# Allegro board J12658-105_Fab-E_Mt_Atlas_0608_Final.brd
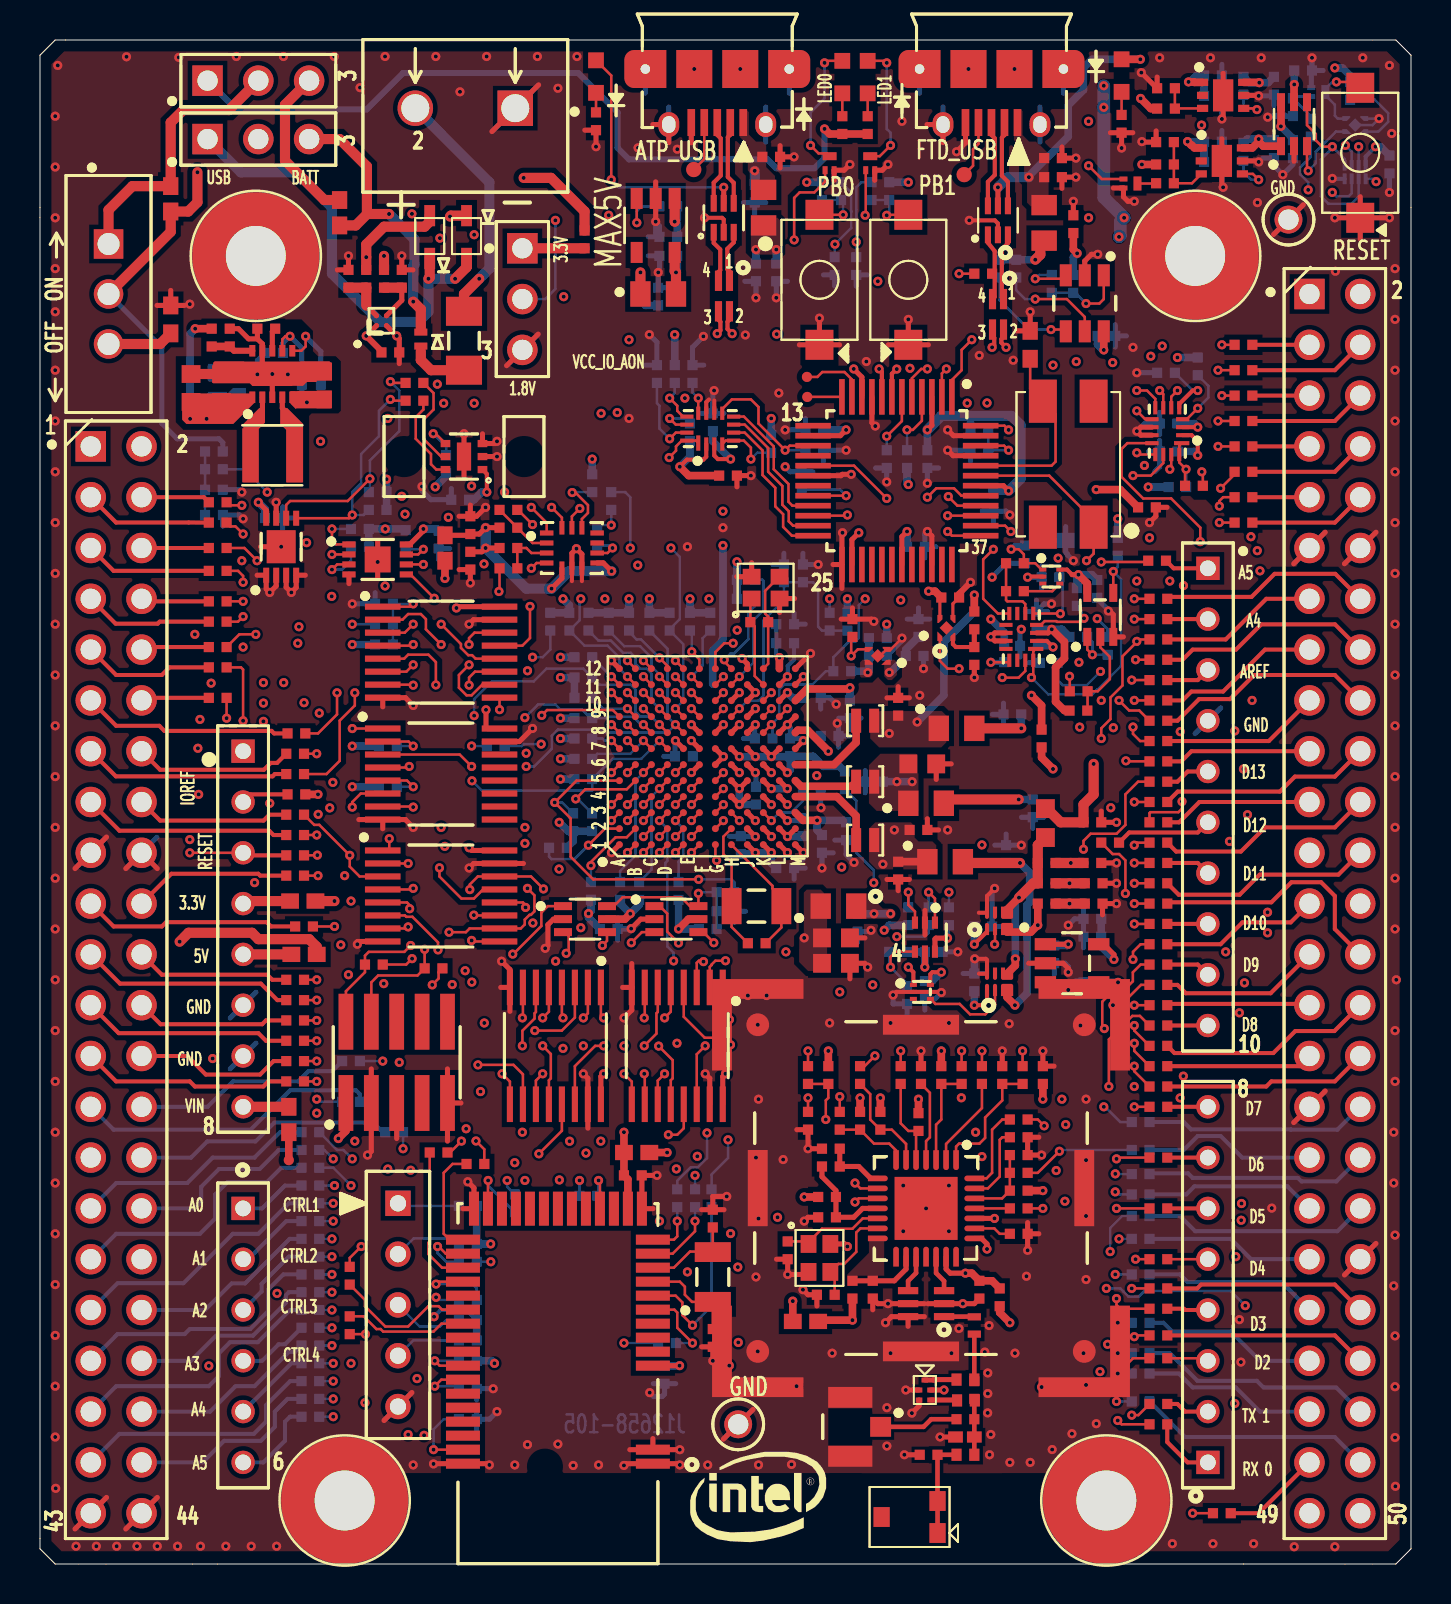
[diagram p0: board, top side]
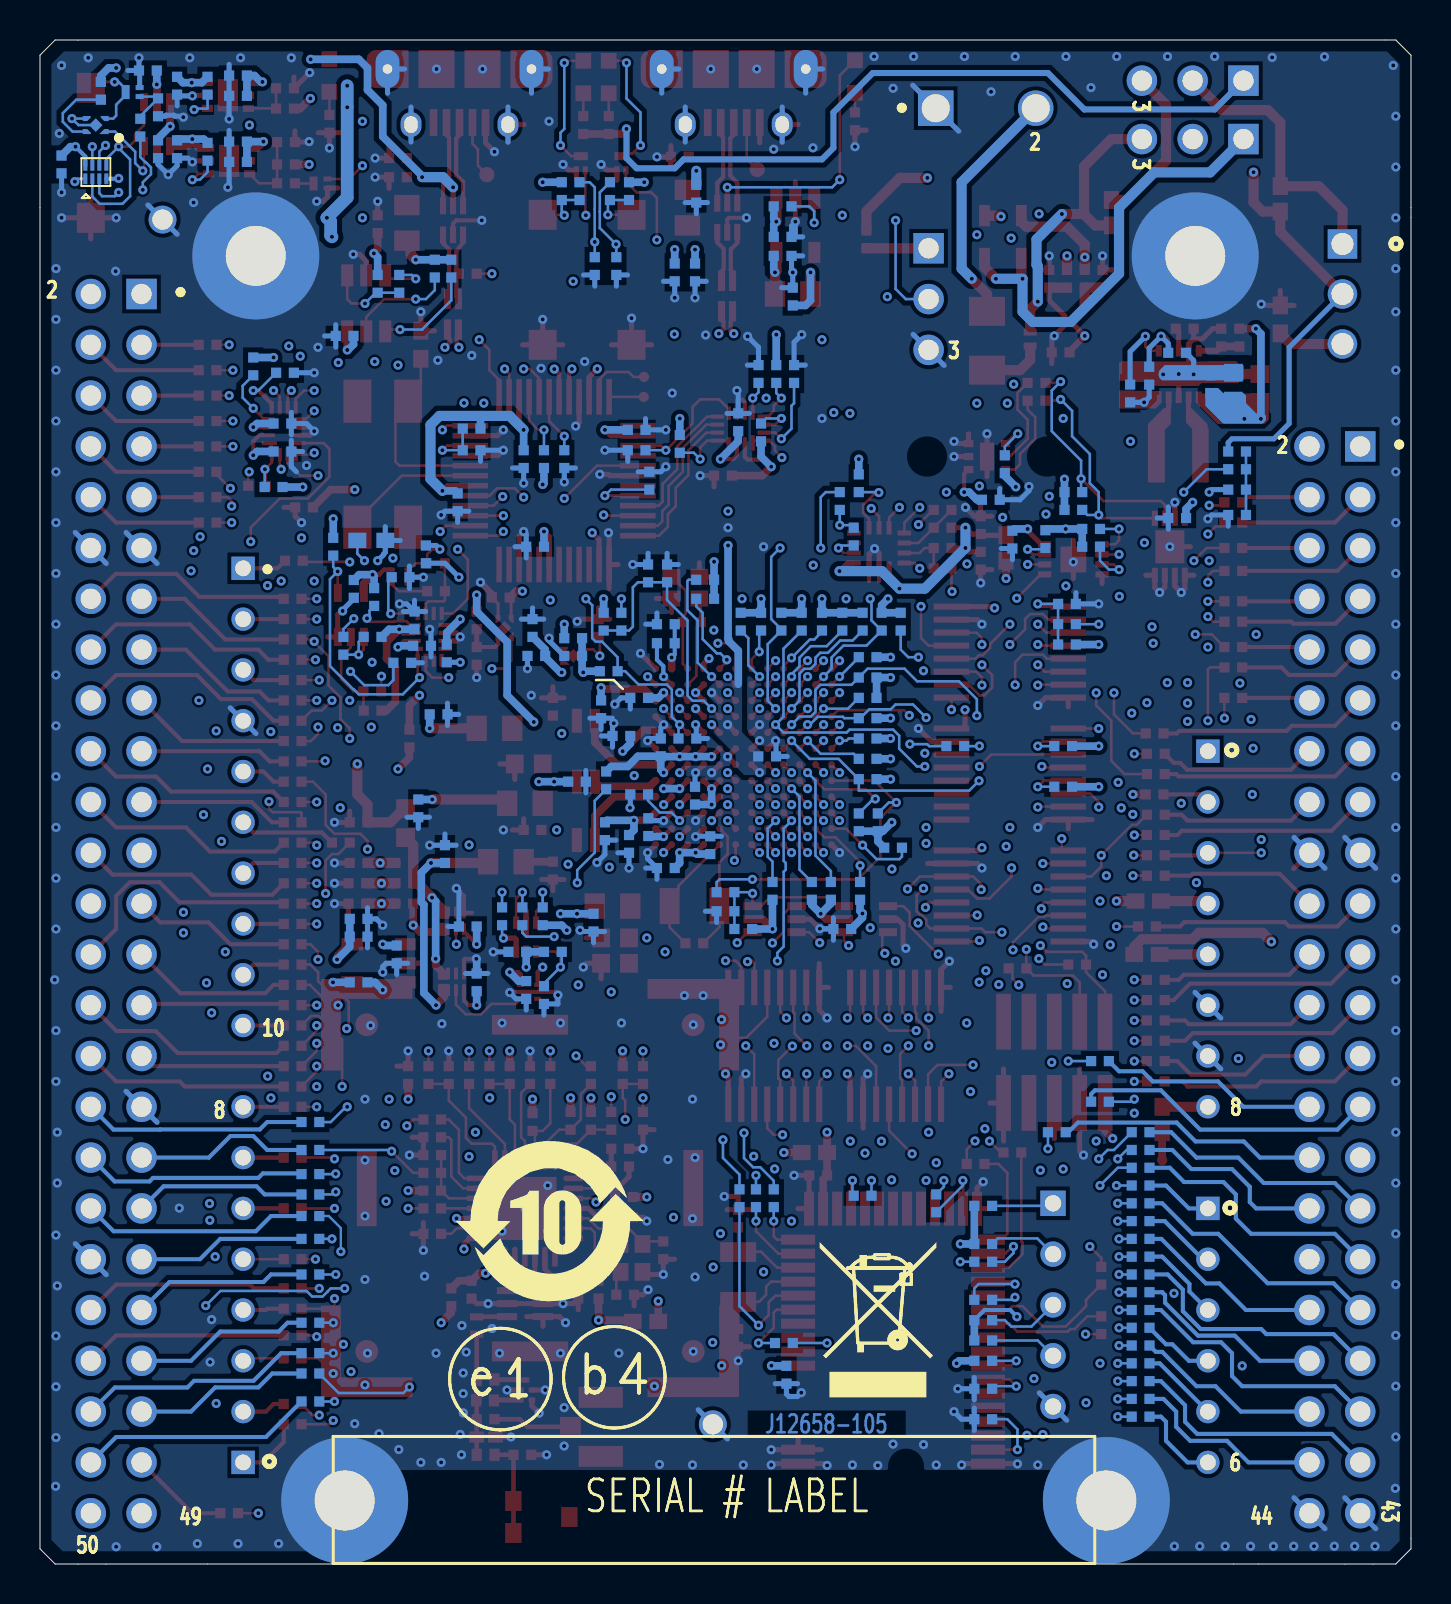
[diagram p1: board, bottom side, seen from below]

Outline 68.58 x 76.2 mm; copper layers: TOP, LAYER2_GND, L3_SIG, L4_SIG, LAYER5_PWR, BOTTOM. Coordinates in mm from the lower left corner of the outline.
Outline path: 0,75.44 0,0.76 0.76,0 67.82,0 68.58,0.76 68.58,75.44 67.82,76.2 0.76,76.2 0,75.44

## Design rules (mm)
net group AP_USB: nets AP_USB_DN AP_USB_DP
net group D_PR: nets D+PR D-PR
net group DPM: nets DM DP
net group FT_D: nets FT_D+P FT_D-P
net group FTD: nets FTD_DM FTD_DP
net group USB_FTD_D: nets USB_FTD_DM USB_FTD_DP
nets with their own width: min track width 0.102; nets VCC_AON_1P8

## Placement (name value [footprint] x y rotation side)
C1  0.1 uF  [SMC0402IA]  36.13 70.36 0 top
C2  0.1 uF  [SMC0402IA]  50.23 70.29 0 top
C3  0.1 uF  [SMC0402IA]  51.69 66.55 90 top
C4  0.1 uF  [SMC0402IA]  15.43 63.82 90 top
C5  0.1 uF  [SMC0402IA]  18.1 63.82 90 top
C6  18pF  [SMC0603IA]  49.53 60.26 90 top
C7  10uF  [SMC0603IA]  14.22 58.23 90 top
C8  4.7UF  [SMC0402IA]  17.08 60.58 0 top
C9  0.1 uF  [SMC0402IA]  49.09 42.48 180 bottom
C10  10uF  [SMC0603IB]  9.08 58.1 90 top
C11  10uF  [SMC0603IB]  8.89 58.17 90 bottom
C12  10uF  [SMC0603IB]  7.56 58.1 90 top
C13  4.7UF  [SMC0402IA]  54.93 52.83 0 top
C14  0.1uF  [SMC0402IA]  21.53 51.5 90 top
C15  0.1uF  [SMC0402IA]  21.53 50.61 270 top
C16  18pF  [SMC0603IA]  52.71 51.18 180 bottom
C17  0.1 uF  [SMC0402IA]  43.94 46.35 90 bottom
C18  1uF  [SMC0402IA]  43.31 45.4 0 bottom
C19  10uF  [SMC0603IB]  43.43 40 0 top
C20  4.7UF  [SMC0402IA]  42.93 42.42 90 top
C21  4.7UF  [SMC0402IA]  43.5 36.7 0 top
C22  1uF  [SMC0402IA]  52.2 35.05 0 top
C23  4.7UF  [SMC0402IA]  52.2 37.08 0 top
C24  4.7UF  [SMC0402IA]  52.26 33.02 0 top
C25  4.7UF  [SMC0402IA]  40.32 37.08 270 bottom
C26  1uF  [SMC0402IA]  52.26 34.04 0 top
C27  10uF  [SMC0603IB]  39.12 31.31 0 top
C28  0.1uF  [SMC0402IA]  11.25 52.3 0 bottom
C29  0.1uF  [SMC0402IA]  19.94 51.66 270 bottom
C30  10uF  [SMC0603IB]  39.12 30.04 0 top
C31  1uF  [SMC0402IA]  50.16 24 90 top
C32  0.1uF  [SMC0402IA]  48.51 21.34 0 top
C33  0.1uF  [SMC0402IA]  40.01 20.76 180 top
C34  0.1uF  [SMC0402IA]  29.21 19.43 0 top
C35  0.1uF  [SMC0402IA]  39.81 17.34 180 top
C36  12pF  [SMC0402IA]  33.66 16.83 90 top
C37  12pF  [SMC0402IA]  37.4 16.13 270 top
C38  0.1uF  [SMC0402IA]  41.66 14.16 270 top
C39  0.1uF  [SMC0402IA]  46.99 14.16 270 top
C40  12pF  [SMC0402IA]  39.75 13.46 180 top
C41  12pF  [SMC0402IA]  33.66 11.75 270 top
C42  2.2pF  [SMC0402IB]  46.74 6.35 180 top
C43  0.1uF  [SMC0402IA]  44.89 5.46 180 top
C44  1uF  [SMC0402IA]  58.23 74.42 0 bottom
C45  0.1uF  [SMC0402IA]  61.72 74.36 270 bottom
C46  0.1uF  [SMC0402IA]  58.23 73.41 0 bottom
C47  1uF  [SMC0402IA]  58.23 71.12 0 bottom
C48  0.1uF  [SMC0402IA]  61.72 71.18 270 bottom
C49  0.1uF  [SMC0402IA]  58.23 70.1 0 bottom
C50  0.1 uF  [SMC0402IA]  31.88 66.36 180 bottom
C51  0.1 uF  [SMC0402IA]  31.88 65.41 180 bottom
C52  4.7UF  [SMC0402IA]  36.83 65.02 270 bottom
C53  0.1 uF  [SMC0402IA]  35.81 65.02 270 bottom
C54  0.1 uF  [SMC0402IA]  52.9 61.4 0 bottom
C55  0.1uF  [SMC0402IA]  11.76 61.77 180 top
C56  0.1uF  [SMC0402IA]  10.03 58.55 90 bottom
C57  0.1 uF  [SMC0402IA]  56.9 57.02 180 bottom
C58  0.1 uF  [SMC0402IA]  39.18 56.71 180 bottom
C59  0.1 uF  [SMC0402IA]  47.43 55.69 180 bottom
C60  0.1 uF  [SMC0402IA]  56.9 55.63 180 bottom
C61  0.1 uF  [SMC0402IA]  44.39 55.69 270 bottom
C62  0.033uF  [SMC0402IA]  42.35 55.69 270 bottom
C63  0.1 uF  [SMC0402IA]  42.16 39.12 180 bottom
C64  1uF  [SMC0402IA]  21.46 53.21 180 bottom
C65  0.1 uF  [SMC0402IA]  47.69 53.53 270 bottom
C66  0.1 uF  [SMC0402IA]  33.66 56.64 90 bottom
C67  0.1uF  [SMC0402IA]  62.67 71.18 270 bottom
C68  0.1uF  [SMC0402IA]  67.5 70.42 270 bottom
C69  0.1 uF  [SMC0402IA]  43.37 50.86 0 bottom
C70  0.1 uF  [SMC0402IA]  33.97 54.42 0 top
C71  0.1 uF  [SMC0402IA]  49.85 46.74 90 bottom
C72  0.1uF  [SMC0402IA]  46.74 28.64 90 bottom
C73  0.1 uF  [SMC0402IA]  49.91 45.91 180 bottom
C74  0.1uF  [SMC0402IA]  36.83 46.99 0 bottom
C75  0.1uF  [SMC0402IA]  38.16 49.09 90 bottom
C76  0.1 uF  [SMC0402IA]  49.66 38.23 270 bottom
C77  0.1uF  [SMC0402IA]  40.51 43.18 270 bottom
C78  0.1uF  [SMC0402IA]  39.05 41.4 0 bottom
C79  0.1uF  [SMC0402IA]  32.65 40.38 180 bottom
C80  0.1uF  [SMC0402IA]  44.26 30.61 0 bottom
C81  0.1 uF  [SMC0402IA]  37.53 40.39 90 bottom
C82  0.1uF  [SMC0402IA]  35.81 37.97 90 bottom
C83  0.1 uF  [SMC0402IA]  38.15 36.4 90 bottom
C84  0.1 uF  [SMC0402IA]  39.12 36.45 270 bottom
C85  0.1uF  [SMC0402IA]  35.05 35.5 90 bottom
C86  0.1 uF  [SMC0402IA]  48.32 35.05 90 bottom
C87  0.1 uF  [SMC0402IA]  42.93 35.12 270 top
C88  4.7UF  [SMC0402IA]  36.83 34.8 0 bottom
C89  0.1 uF  [SMC0402IA]  28 31.75 0 bottom
C90  0.1uF  [SMC0402IA]  50.74 30.92 270 bottom
C91  0.1 uF  [SMC0402IA]  40.89 32.51 270 bottom
C92  0.1uF  [SMC0402IA]  53.09 32.26 180 bottom
C93  4.7UF  [SMC0402IA]  53.09 31.37 180 bottom
C94  1uF  [SMC0402IA]  31.24 9.91 270 bottom
C95  0.1 uF  [SMC0402IA]  20.95 7.24 0 bottom
C96  0.1uF  [SMC0402IA]  52.88 49.2 270 bottom
C97  0.1uF  [SMC0402IA]  8.25 53.72 0 bottom
C98  1uF  [SMC0402IA]  41.47 45.4 0 bottom
C99  0.1uF  [SMC0402IA]  46.74 31.88 0 bottom
C100  0.1uF  [SMC0402IA]  44.26 29.15 270 bottom
C101  0.1uF  [SMC0402IA]  46.74 45.85 270 top
C102  0.1uF  [SMC0402IA]  45.09 48.32 0 top
C103  0.1uF  [SMC0402IA]  62.74 74.68 0 bottom
C104  0.1uF  [SMC0402IA]  40.83 65.34 270 bottom
C105  0.1uF  [SMC0402IA]  39.75 65.34 270 bottom
D1  -  [SLED0603IB]  54.1 75.23 270 top
D2  -  [SLED0603IB]  27.81 75.18 270 top
D3  -  [SLEDR0603IA]  40.13 73.53 90 top
D4  -  [SLEDR16X08MA]  41.4 73.53 90 top
D6  23V  [QT_SOD_323]  21.34 65.28 90 top
D7  23V  [QT_SOD_323]  19.49 65.28 90 top
D8  PMEG2005AEL  [SCR1006MA]  19.05 61.59 270 top
F1  -  [SFU1206IA]  21.21 59.69 90 top
FB1  30OHM  [SFB0603IA]  6.54 67.62 90 top
FB2  100OHM  [SFB0805IA]  36.2 66.93 90 top
FB3  30OHM  [SFB0603IA]  14.99 68.2 270 top
FB4  100OHM  [SFB0805IA]  50.23 66.17 90 top
FB5  100OHM  [SFB0805IA]  30.04 63.5 0 top
FB6  30OHM  [SFB0603IA]  20.26 50.16 90 top
FB7  100OHM  [SFB0805IA]  43.43 38.04 0 top
FB8  100OHM  [SFB0805IA]  44.96 41.78 0 top
FB9  100OHM  [SFB0805IA]  44.39 35.12 0 top
FB10  30OHM  [SFB0603IA]  13.78 33.15 180 top
FB11  100OHM  [SFB0805IA]  40.83 32.89 180 top
FB12  30OHM  [SFB0603IA]  13.84 30.48 180 top
FB13  30OHM  [SFB0603IA]  12.45 21.59 90 top
FB14  30OHM  [SFB0603IA]  30.48 20.57 180 top
FB15  30OHM  [SFB0603IA]  37.66 12.13 0 top
FB16  120OHM  [SFB0603IB]  50.29 36.32 90 top
FL1  -  [QT_USMM_QCS5F_B9413]  44.26 8.7 270 top
HW1  -  [QT_SMCC_LEADERTECH_SMS_201]  44.07 18.8 0 top
J1  -  [QT_CN_HIROSE_ZX62D_B_5P8]  35.18 72.07 180 top
J2  -  [QT_CN_HIROSE_ZX62D_B_5P8]  48.9 72.07 180 top
J3  -  [QT_JTHI_SAMTEC_TSW_103_07_G_S]  8.38 74.17 90 top
J4  -  [HDR_TJV_1X2_50MA]  23.77 72.79 270 top
J5  -  [QT_JTHI_SAMTEC_TSW_103_07_G_S]  8.38 71.25 90 top
J6  -  [QT_JTHI_SAMTEC_TSW_103_07_G_S]  24.13 65.79 0 top
J8  -  [QT_JSMM_MOLEX_90147_1110_PTH031]  58.42 49.78 0 top
J9  -  [QT_JSMM_MOLEX_90147_1108_PTH031]  10.16 40.64 0 top
J10  -  [QT_JSMM_SAMTEC_FTSH_105]  17.84 25.08 270 top
J11  -  [QT_JSMM_MOLEX_90147_1108_PTH031]  58.42 5.08 180 top
J12  -  [QT_JSMM_MOLEX_90147_1106_PTH031]  10.16 17.78 0 top
J13  -  [SMP_SJV_1_2EM_MA]  42.05 6.86 270 top
J14  -  [QT_JTHI_HDR_2X25_0P040D]  63.5 63.5 0 top
J15  -  [QT_JTHI_HDR_2X22_0P040D]  2.54 55.88 0 top
J20  -  [TP_C55P40A65]  34.92 6.98 0 top
J21  -  [TP_C55P40A65]  62.45 67.22 0 top
L1  80.0OHM  [SMI4_10X13MA]  34.49 64.16 270 top
L2  80.0OHM  [SMI4_10X13MA]  48.2 63.25 270 top
L3  -  [QT_IND_MDKK3030_0P8X2P7]  11.62 55.44 0 top
L4  -  [QT_IND_PSB12101T_1P45X1P2]  41.27 42.16 0 top
L5  -  [QT_IND_PSB12101T_1P45X1P2]  41.27 39.12 0 top
L6  -  [QT_IND_PSB12101T_1P45X1P2]  41.27 36.2 0 top
L7  -  [QT_LSMI_COILCRAFT_0402HP]  46.74 12.36 270 top
L8  1.5nH  [SMI0402IA]  46.74 9.22 180 top
L9  2.5nH  [SMI0402IA]  45.87 8.18 0 top
L10  4.7nH  [SMI0402IA]  46.74 5.46 180 top
LB1  -  [LB_10_IA]  43.05 17.14 180 bottom
LB3  -  [LB_B4_IA]  39.85 9.34 180 bottom
LB4  -  [LB_E1_IA]  45.55 9.25 180 bottom
LB5  -  [LB_SN_IA]  34.87 6.38 180 bottom
MH1  -  [QT_MHTHI_PTH_250R118]  10.79 65.41 0 top
MH2  -  [QT_MHTHI_PTH_250R118]  57.79 65.41 0 top
MH3  -  [QT_MHTHI_PTH_250R118]  15.24 3.17 0 top
MH4  -  [QT_MHTHI_PTH_250R118]  53.34 3.17 0 top
NOREF  -  []  0 0.63 0 top
NOREF#2  -  []  35.75 3.49 0 top
NOREF#3  -  []  68.58 76.2 0 top
NOREF#4  -  []  -20.32 -99.19 0 top
NOREF#5  -  []  3.81 3.81 0 top
NOREF#6  -  []  0 75.44 0 top
NOREF#7  -  []  15.24 3.17 0 top
NOREF#8  -  []  3.81 3.81 0 top
NOREF#9  -  []  0.63 0 0 top
NOREF#10  -  []  19.43 4.25 0 top
NOREF#11  -  []  68.58 43.48 0 top
NOREF#12  -  []  15.18 0 0 top
NOREF#13  -  []  0 39.3 0 top
NOREF#14  -  []  54.33 0 0 top
NOREF#15  -  []  283.85 -144.53 0 top
NOREF#16  -  []  32.33 30.56 0 top
NOREF#17  -  []  68.58 0.63 0 top
NOREF#18  -  []  3.75 3.87 0 top
NOREF#19  -  []  67.82 0 90 top
NOREF#20  -  []  265.56 69.6 0 top
NOREF#21  -  []  -357.12 252.22 0 top
NOREF#22  -  []  -365.63 -244.98 0 top
NOREF#23  -  []  -346.33 244.73 0 top
NOREF#24  -  []  0.63 76.2 0 top
NOREF#25  -  []  36.2 29.27 0 top
NOREF#26  -  []  26.67 12.19 180 bottom
Q1  -  [QT_QSMM_SOT883B]  63.94 73.6 0 bottom
Q2  -  [QT_QSMM_SOT883B]  54.55 69.02 0 top
Q4  -  [QT_QSMM_SOT883B]  41.53 70.04 90 top
Q5  -  [QT_QSMM_SOT883B]  39.5 70.04 90 top
R1  2.94K  [SMR0402IA]  27.81 72.58 270 top
R2  1.1K  [SMR0402IA]  40.13 71.5 90 top
R3  1.1K  [SMR0402IA]  41.4 71.5 90 top
R4  2.94K  [SMR0402IA]  54.1 72.45 270 top
R5  0  [SMR0402IA]  46.74 47.62 270 top
R6  10.0K  [SMR0402IA]  50.23 69.34 0 top
R7  100K  [SMR0402IA]  27.24 66.67 270 top
R8  1.5K  [SMR0402IA]  47.62 64.52 180 top
R9  0  [SMR0402IA]  16.32 64.71 270 top
R10  100K  [SMR0402IA]  17.21 64.71 270 top
R11  10.0K  [SMR0402IA]  35.75 68.96 270 bottom
R12  33  [SMR0402IA]  59.75 60.96 0 top
R13  147K  [SMR0402IA]  8.59 61.77 270 top
R14  33  [SMR0402IA]  60.64 59.69 180 top
R15  0  [SMR0402IA]  14.05 58.08 90 bottom
R16  33  [SMR0402IA]  59.75 58.42 0 top
R17  300  [SMR0603IA]  6.54 61.53 90 top
R18  33  [SMR0402IA]  60.64 57.15 180 top
R19  33  [SMR0402IA]  59.75 55.88 0 top
R20  33  [SMR0402IA]  8.45 53.09 0 top
R21  33  [SMR0402IA]  60.64 54.61 180 top
R22  33  [SMR0402IA]  59.75 53.34 0 top
R23  33  [SMR0402IA]  9.33 52.07 180 top
R24  10.0K  [SMR0402IA]  22.99 51.82 90 top
R25  0  [SMR0402IA]  23.88 52.7 270 top
R26  33  [SMR0402IA]  60.64 52.07 180 top
R27  33  [SMR0402IA]  8.45 50.8 0 top
R28  10.0K  [SMR0402IA]  22.99 50.8 0 top
R29  33  [SMR0402IA]  56.32 50.16 180 top
R30  0  [SMR0402IA]  22.99 49.78 0 top
R31  10.0K  [SMR0402IA]  49.28 50.04 90 bottom
R32  33  [SMR0402IA]  9.33 49.66 180 top
R33  36K  [SMR0402IA]  40.58 44.64 180 bottom
R34  33  [SMR0402IA]  56.39 48.26 180 top
R35  33  [SMR0402IA]  8.45 48.13 0 top
R36  33  [SMR0402IA]  56.39 47.24 180 top
R37  33  [SMR0402IA]  9.33 47.12 180 top
R38  33  [SMR0402IA]  55.5 46.23 0 top
R39  33  [SMR0402IA]  8.45 45.85 0 top
R40  33  [SMR0402IA]  56.39 45.21 180 top
R41  33  [SMR0402IA]  9.33 44.83 180 top
R42  33  [SMR0402IA]  56.39 44.2 180 top
R43  33  [SMR0402IA]  8.45 43.31 0 top
R44  33  [SMR0402IA]  55.5 43.18 0 top
R45  33  [SMR0402IA]  56.39 42.16 180 top
R46  33  [SMR0402IA]  13.27 41.53 180 top
R47  33  [SMR0402IA]  55.5 41.15 0 top
R48  33  [SMR0402IA]  12.32 40.51 0 top
R49  33  [SMR0402IA]  55.5 40.13 0 top
R50  33  [SMR0402IA]  13.21 39.5 180 top
R51  33  [SMR0402IA]  56.39 39.12 180 top
R52  0  [SMR0402IA]  13.27 38.48 180 top
R53  33  [SMR0402IA]  56.39 38.1 180 top
R54  33  [SMR0402IA]  12.32 37.46 0 top
R55  33  [SMR0402IA]  55.5 37.08 0 top
R56  33  [SMR0402IA]  13.21 36.45 180 top
R57  0  [SMR0402IA]  49.91 35.05 0 top
R58  33  [SMR0402IA]  53.98 36.07 180 top
R59  33  [SMR0402IA]  56.39 36.07 180 top
R60  33  [SMR0402IA]  13.21 35.43 180 top
R61  0  [SMR0402IA]  40.64 46.35 90 top
R62  33  [SMR0402IA]  56.39 35.05 180 top
R63  33  [SMR0402IA]  12.32 34.42 0 top
R64  0  [SMR0402IA]  50.8 33.02 180 top
R65  33  [SMR0402IA]  56.39 34.04 180 top
R66  0  [SMR0402IA]  49.91 34.04 0 top
R67  33  [SMR0402IA]  56.39 33.02 180 top
R68  33  [SMR0402IA]  56.39 32 180 top
R69  33  [SMR0402IA]  13.65 31.88 180 top
R70  33  [SMR0402IA]  55.5 30.99 0 top
R71  10M  [SMR0402IA]  36.3 31.04 180 top
R72  33  [SMR0402IA]  56.39 29.97 180 top
R73  33  [SMR0402IA]  12.32 29.21 0 top
R74  33  [SMR0402IA]  55.5 28.96 0 top
R75  33  [SMR0402IA]  13.21 28.19 180 top
R76  33  [SMR0402IA]  55.5 27.94 0 top
R77  33  [SMR0402IA]  12.32 27.18 0 top
R78  33  [SMR0402IA]  56.39 26.92 180 top
R79  33  [SMR0402IA]  13.21 26.16 180 top
R80  33  [SMR0402IA]  56.39 25.91 180 top
R81  33  [SMR0402IA]  12.32 25.15 0 top
R82  33  [SMR0402IA]  55.5 24.89 0 top
R83  33  [SMR0402IA]  38.42 24.89 270 top
R84  100K  [SMR0402IA]  39.43 24.89 270 top
R85  33  [SMR0402IA]  41.02 24.89 270 top
R86  33  [SMR0402IA]  43.05 24.89 270 top
R87  100K  [SMR0402IA]  44.07 24 90 top
R88  100K  [SMR0402IA]  45.09 24.89 270 top
R89  33  [SMR0402IA]  46.1 24.89 270 top
R90  33  [SMR0402IA]  47.12 24.89 270 top
R91  1M  [SMR0402IA]  48.13 24 90 top
R92  33  [SMR0402IA]  49.15 24.89 270 top
R93  33  [SMR0402IA]  13.21 24.13 180 top
R94  33  [SMR0402IA]  56.39 23.88 180 top
R95  33  [SMR0402IA]  56.39 22.86 180 top
R96  33  [SMR0402IA]  49.4 22.23 180 top
R97  100K  [SMR0402IA]  38.42 22.61 270 top
R98  33  [SMR0402IA]  40.01 22.61 270 top
R99  100K  [SMR0402IA]  41.02 22.61 270 top
R100  100K  [SMR0402IA]  42.04 22.61 270 top
R101  100K  [SMR0402IA]  43.94 22.54 270 top
R102  100K  [SMR0402IA]  48.51 20.45 0 top
R103  33  [SMR0402IA]  56.39 20.32 180 top
R104  0  [SMR0402IA]  40.01 19.88 180 top
R105  33  [SMR0402IA]  49.4 19.56 180 top
R106  100K  [SMR0402IA]  49.4 18.67 180 top
R107  0  [SMR0402IA]  38.93 18.35 0 top
R108  33  [SMR0402IA]  49.4 17.78 180 top
R109  33  [SMR0402IA]  56.39 17.78 180 top
R110  56.2K  [SMR0402IA]  48.51 16.51 0 top
R111  33  [SMR0402IA]  56.39 10.29 180 top
R112  33  [SMR0402IA]  56.39 13.78 180 top
R113  0  [SMR0402IA]  40.64 13.27 90 top
R114  0  [SMR0402IA]  48.01 12.89 90 top
R115  33  [SMR0402IA]  56.39 12.76 180 top
R116  33  [SMR0402IA]  56.39 11.43 180 top
R117  33  [SMR0402IA]  56.39 15.24 180 top
R118  0  [SMR0402IA]  46.74 9.14 270 top
R119  33  [SMR0402IA]  56.39 8 180 top
R120  0  [SMR0402IA]  46.74 7.24 180 top
R121  33  [SMR0402IA]  56.39 6.98 180 top
R122  10.0K  [SMR0402IA]  62.67 73.28 270 bottom
R123  162K  [SMR0402IA]  56.77 73.79 180 top
R124  0  [SMR0402IA]  60.2 74.36 270 bottom
R125  0  [SMR0402IA]  65.53 74.1 270 bottom
R126  280K  [SMR0402IA]  55.88 72.77 0 top
R127  0  [SMR0402IA]  9.14 54.74 180 bottom
R128  0  [SMR0402IA]  63.56 72.26 270 bottom
R129  100K  [SMR0402IA]  32.51 56.13 90 bottom
R130  590K  [SMR0402IA]  56.72 71.09 180 top
R131  0  [SMR0402IA]  60.2 71.06 270 bottom
R132  280K  [SMR0402IA]  55.83 69.98 0 top
R133  226K  [SMR0402IA]  56.72 69.04 180 top
R134  100K  [SMR0402IA]  42.48 69.09 270 bottom
R135  330  [SMR0402IA]  41.59 68.2 90 bottom
R136  330  [SMR0402IA]  40.07 68.2 90 bottom
R137  100K  [SMR0402IA]  39.12 69.09 270 bottom
R138  0  [SMR0402IA]  31.88 67.88 180 bottom
R139  10.0K  [SMR0402IA]  51.69 64.45 270 bottom
R140  2.05K  [SMR0402IA]  50.61 64.45 270 bottom
R141  10.0K  [SMR0402IA]  30.92 62.93 90 bottom
R142  0  [SMR0402IA]  12.14 60.56 180 bottom
R143  0  [SMR0402IA]  13.1 58.97 90 bottom
R144  22.1K  [SMR0402IA]  9.49 60.88 90 top
R145  10.0K  [SMR0402IA]  57.91 60.32 270 bottom
R146  10.0K  [SMR0402IA]  56.77 59.56 180 bottom
R147  475  [SMR0402IA]  46.55 56.77 0 bottom
R148  10.0K  [SMR0402IA]  38.29 55.69 0 bottom
R149  10.0K  [SMR0402IA]  43.37 54.8 90 bottom
R150  100K  [SMR0402IA]  20.32 54.55 90 bottom
R151  10.0K  [SMR0402IA]  38.1 53.72 90 bottom
R152  100K  [SMR0402IA]  27.62 54.48 270 bottom
R153  2.94K  [SMR0402IA]  17.34 53.59 180 bottom
R154  10.0K  [SMR0402IA]  53.91 51.31 270 bottom
R155  10.0K  [SMR0402IA]  51.5 42.67 0 top
R156  0  [SMR0402IA]  28.58 53.59 270 bottom
R157  2.94K  [SMR0402IA]  17.34 52.7 180 bottom
R158  10.0K  [SMR0402IA]  51.5 46.35 0 bottom
R159  100K  [SMR0402IA]  16.45 51.75 180 bottom
R160  0  [SMR0402IA]  53.4 46.35 270 bottom
R161  10.0K  [SMR0402IA]  36.58 56.45 270 bottom
R162  0  [SMR0402IA]  27.88 50.93 90 bottom
R163  100K  [SMR0402IA]  18.29 51.69 270 bottom
R164  10M  [SMR0402IA]  35.53 47.09 0 top
R165  100K  [SMR0402IA]  16.45 50.86 180 bottom
R166  0  [SMR0402IA]  51.51 43.64 0 top
R167  10.0K  [SMR0402IA]  50.9 45.06 180 bottom
R168  0  [SMR0402IA]  58.17 53.91 180 top
R169  0  [SMR0402IA]  39.5 47.56 270 bottom
R170  10.0K  [SMR0402IA]  40.39 47.56 270 bottom
R171  10.0K  [SMR0402IA]  37.21 49.09 90 bottom
R172  100K  [SMR0402IA]  34.86 49.21 0 bottom
R173  100K  [SMR0402IA]  34.86 48.26 0 bottom
R174  100K  [SMR0402IA]  33.53 47.56 270 bottom
R175  100K  [SMR0402IA]  32.51 47.56 270 bottom
R176  100K  [SMR0402IA]  31.5 47.56 270 bottom
R177  100K  [SMR0402IA]  30.48 47.56 270 bottom
R178  100K  [SMR0402IA]  29.46 47.56 270 bottom
R179  2.94K  [SMR0402IA]  28.45 47.56 270 bottom
R180  100K  [SMR0402IA]  27.43 47.56 270 bottom
R181  2.94K  [SMR0402IA]  26.48 47.56 270 bottom
R182  2.94K  [SMR0402IA]  25.53 47.56 270 bottom
R183  0  [SMR0402IA]  16.76 46.99 0 bottom
R184  0  [SMR0402IA]  49.21 48.64 180 top
R185  2.94K  [SMR0402IA]  26.73 45.34 0 bottom
R186  10.0K  [SMR0402IA]  51.87 48.79 270 bottom
R187  2.94K  [SMR0402IA]  16.95 38.86 0 bottom
R188  100K  [SMR0402IA]  17.65 48.01 180 bottom
R189  100K  [SMR0402IA]  16.76 45.97 0 bottom
R190  100K  [SMR0402IA]  26.73 44.32 0 bottom
R191  2.94K  [SMR0402IA]  16.95 40.89 0 bottom
R192  0  [SMR0402IA]  38.16 43.31 0 bottom
R193  100K  [SMR0402IA]  26.73 43.31 0 bottom
R194  100K  [SMR0402IA]  26.73 42.29 0 bottom
R195  0  [SMR0402IA]  15.49 14.86 270 top
R196  0  [SMR0402IA]  45.47 32.83 270 bottom
R197  100K  [SMR0402IA]  43.43 31.94 90 bottom
R198  0  [SMR0402IA]  44.45 31.94 90 bottom
R199  22.1K  [SMR0402IA]  36.64 41.27 180 bottom
R200  100K  [SMR0402IA]  26.73 41.27 0 bottom
R201  100K  [SMR0402IA]  26.73 40.26 0 bottom
R202  100K  [SMR0402IA]  26.73 39.24 0 bottom
R203  100K  [SMR0402IA]  43.37 30.61 180 bottom
R204  0  [SMR0402IA]  43.37 28.89 270 bottom
R205  100K  [SMR0402IA]  27.62 36.64 90 bottom
R206  100K  [SMR0402IA]  26.67 36.64 90 bottom
R207  100K  [SMR0402IA]  26.35 35.81 180 bottom
R208  0  [SMR0402IA]  48.32 50.04 0 top
R209  100K  [SMR0402IA]  31.94 33.21 90 bottom
R210  100K  [SMR0402IA]  29.97 33.21 90 bottom
R211  100K  [SMR0402IA]  29.02 33.21 90 bottom
R212  100K  [SMR0402IA]  27.56 33.21 90 bottom
R213  0  [SMR0402IA]  40.26 39.62 270 bottom
R214  0  [SMR0402IA]  34.73 33.59 180 bottom
R215  0  [SMR0402IA]  53.09 29.08 180 bottom
R216  33  [SMR0402IA]  15.11 25.15 0 bottom
R217  33  [SMR0402IA]  15.11 23.11 0 bottom
R218  33  [SMR0402IA]  55.5 22.1 180 bottom
R219  33  [SMR0402IA]  17.27 21.59 0 bottom
R220  33  [SMR0402IA]  13.97 21.59 180 bottom
R221  33  [SMR0402IA]  54.61 20.7 0 bottom
R222  33  [SMR0402IA]  13.08 20.7 0 bottom
R223  33  [SMR0402IA]  13.97 19.81 180 bottom
R224  33  [SMR0402IA]  55.5 19.49 180 bottom
R225  33  [SMR0402IA]  13.97 18.92 180 bottom
R226  33  [SMR0402IA]  54.61 18.48 0 bottom
R227  0  [SMR0402IA]  27.88 18.41 180 bottom
R228  0  [SMR0402IA]  32.77 17.84 90 bottom
R229  0  [SMR0402IA]  31.88 17.84 90 bottom
R230  0  [SMR0402IA]  23.75 17.59 90 bottom
R231  33  [SMR0402IA]  13.97 18.03 180 bottom
R232  1M  [SMR0402IA]  21.84 17.91 180 bottom
R233  33  [SMR0402IA]  55.5 17.4 180 bottom
R234  33  [SMR0402IA]  13.97 17.14 180 bottom
R235  33  [SMR0402IA]  54.61 16.26 0 bottom
R236  33  [SMR0402IA]  13.08 16.26 0 bottom
R237  1M  [SMR0402IA]  21.84 16 180 bottom
R238  33  [SMR0402IA]  13.97 15.37 180 bottom
R239  0  [SMR0402IA]  20.95 15.11 0 bottom
R240  33  [SMR0402IA]  54.61 14.48 0 bottom
R241  33  [SMR0402IA]  13.97 14.48 180 bottom
R242  33  [SMR0402IA]  13.08 13.59 0 bottom
R243  0  [SMR0402IA]  21.84 13.21 180 bottom
R244  33  [SMR0402IA]  13.97 12.7 180 bottom
R245  0  [SMR0402IA]  33.59 17.84 90 bottom
R246  1M  [SMR0402IA]  21.84 12.19 180 bottom
R247  33  [SMR0402IA]  54.61 12.07 0 bottom
R248  33  [SMR0402IA]  13.97 11.81 180 bottom
R249  1M  [SMR0402IA]  21.84 11.18 180 bottom
R250  0  [SMR0402IA]  31.81 11.05 180 bottom
R251  33  [SMR0402IA]  13.08 10.92 0 bottom
R252  33  [SMR0402IA]  55.5 10.54 180 bottom
R253  100K  [SMR0402IA]  21.84 10.16 180 bottom
R254  33  [SMR0402IA]  13.97 10.03 180 bottom
R255  33  [SMR0402IA]  54.61 9.52 0 bottom
R256  33  [SMR0402IA]  13.97 9.14 180 bottom
R257  12K  [SMR0402IA]  20.95 8.76 0 bottom
R258  33  [SMR0402IA]  13.08 8.25 0 bottom
R259  33  [SMR0402IA]  55.5 8.13 180 bottom
R260  33  [SMR0402IA]  13.97 7.37 180 bottom
R261  33  [SMR0402IA]  58.67 2.54 0 top
R262  0  [SMR0402IA]  39.05 38.48 180 bottom
R263  0  [SMR0402IA]  15.49 11.49 90 top
R264  0  [SMR0402IA]  18.29 58.17 0 top
R265  0  [SMR0402IA]  18.29 59.05 0 top
R266  0  [SMR0402IA]  22.23 20 180 top
R267  0  [SMR0402IA]  20.38 20.57 180 top
R268  0  [SMR0402IA]  16.26 29.97 0 top
R269  0  [SMR0402IA]  19.24 29.78 0 top
R270  10.0K  [SMR0402IA]  48.83 65.21 270 bottom
R271  10.0K  [SMR0402IA]  48.01 65.21 270 bottom
R272  0  [SMR0402IA]  50.1 41.72 270 top
R273  33  [SMR0402IA]  42.35 46.29 180 bottom
R274  100K  [SMR0402IA]  30.86 59.05 90 bottom
R275  100K  [SMR0402IA]  31.75 59.94 270 bottom
R276  100K  [SMR0402IA]  32.64 59.05 90 bottom
R277  100K  [SMR0402IA]  48.23 45.97 270 bottom
R278  1.5K  [SMR0402IA]  36.83 46.04 0 bottom
R279  100K  [SMR0402IA]  9.14 55.63 180 bottom
R280  100K  [SMR0402IA]  8.25 52.45 0 bottom
R281  0  [SMR0402IA]  22.35 40.89 0 bottom
R282  590K  [SMR0402IA]  32.96 31.75 0 bottom
R283  590K  [SMR0402IA]  33.85 32.64 0 bottom
R284  10.0K  [SMR0402IA]  50.99 49.34 180 bottom
R285  10.0K  [SMR0402IA]  56.45 53.85 0 bottom
REF  -  [unnamed#2]  21.21 55.37 180 top
RF1  -  [QT_RFSMM_JOHANSON_2450BM15B0002]  44.32 13.02 270 top
RF2  -  [QT_RFSMM_ANTENOVA_A10192]  43.5 2.35 180 top
S1  -  [QT_SSMI_CK_KSR221GLFS]  66.04 67.31 90 top
SW1  -  [QT_SSMI_CK_KSR221GLFS]  38.99 60.96 90 top
SW2  -  [QT_SSMI_CK_KSR221GLFS]  43.43 60.96 90 top
SW3  -  [SW3VS_116X40_250MA]  3.43 66 0 top
SW4  -  [QT_SWTHI_TYCO_1977104_2]  17.91 18.03 0 top
TP1  -  [TP_C20]  12.45 20.19 0 top
TP3  -  [TP_C20]  38.36 59.35 0 top
TP4  -  [TP_C20]  38.38 58.35 0 top
U1  -  [LCC6_S20_65DF16X10MA]  58.15 74.08 0 top
U2  -  [LCC6_S20_65DF16X10MA]  58.09 70.8 0 top
U3  -  [QT_USMI_SOT666]  34.2 67.31 0 top
U4  -  [QT_USMI_SOT666]  47.92 67.18 0 top
U5  -  [QT_USMI_SOT235]  30.8 66.93 180 top
U6  -  [SOT23_6MC]  53.21 64.17 270 top
U7  -  [QT_USMM_4YZV]  17.08 62.17 90 top
U8  -  [LCC8_16X10_40MA]  47.37 28.7 90 top
U9  -  [QT_USMM_UFQFN16]  56.39 56.64 180 top
U10  -  [QT_USMM_6_UTDFN_OPTO]  21.21 55.37 180 top
U11  -  [QFP48_S70_50MA]  42.86 54.17 270 top
U12  -  [LCC8_20X30_50DF145X165MA]  12.07 50.86 90 top
U13  -  [QT_USMM_UFQFN16]  33.53 56.77 90 top
U14  -  [QT_LCC14_30X25_50MA]  25.34 51.55 0 top
U15  -  [LCC8_30X20_50DF15X13MA]  15.46 50.98 0 top
U16  -  [QT_TDFN_4]  42.32 45.08 180 top
U17  -  [QT_USMM_UFQFN16]  49.09 46.35 180 top
U18  -  [LCC8_16X10_40MA]  47.37 31.75 90 top
U19  -  [TSSOP16_50X44_65MA]  17.14 41.77 0 top
U20  -  [TSSOP16_50X44_65MA]  17.14 47.87 0 top
U21  -  [SOT563A]  44.77 32.07 270 top
U22  -  [QT_USMM_PG_LFBGA144_10]  33.4 40.39 90 top
U23  -  [TSSOP16_50X44_65MA]  17.14 35.68 0 top
U24  -  [QT_SOT_953]  43.69 28.96 0 top
U25  -  [TSSOP16_50X44_65MA]  34.15 28.83 270 top
U26  -  [QT_TDFN_4]  45.01 46.39 90 top
U27  -  [SOT23_5MC]  50.29 30.99 0 top
U28  -  [TSSOP16_50X44_65MA]  28.06 28.83 270 top
U29  -  [QT_USMM_VQFN28]  44.32 17.78 270 top
U30  -  [QT_LCC42_180X100_70MA]  25.91 9.02 180 top
U31  -  [QT_TDFN_4]  65.38 71.62 0 bottom
U32  -  [QT_P2XSON-8]  65.79 69.6 90 bottom
U33  -  [QT_USMM_SC70_6]  26.16 32.89 0 top
U34  -  [QT_TPSMI_30]  32.7 69.72 0 top
U35  -  [QT_TPSMI_30]  46.23 69.47 0 top
U36  -  [QT_USMM_SC70_6]  62.08 70.89 90 top
U37  -  [QT_SOT_953]  50.16 49.72 0 top
U38  -  [QT_USMM_SC70_6]  30.73 32.89 0 top
U39  -  [QT_USMM_SC70_5]  52.39 46.35 90 top
U40  -  [LCC10_S25_50DF20X12MA]  10.62 58.34 90 top
Y1  -  [QT_YSMM_ABRACON_ABMM]  51.44 54.99 90 top
Y2  -  [QT_YSMM_PSE_FW3200020]  36.3 48.82 0 top
Y3  -  [SMY32X15MA]  37.08 32.89 180 top
Y4  -  [QT_YSMM_PSE_FW3200020]  38.99 15.3 270 top
Y5  -  [SMY32X15MA]  33.66 13.11 90 top

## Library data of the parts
C1-C5 C9 C17 C50 C51 C53 C54 C57-C61 C63 C65 C66 C69-C71 C73 C76 C81 C83 C84 C86 C87 C89 C91 C95 = CAP: alternate symbols: (); part number: CAP_0402-H75782-001,X7R,0.1 UF,16V,10%
C6 C16 = CAP: alternate symbols: (); part number: CAP_0603-603275-161,C0G,18PF,50V,5%
C7 = CAP: alternate symbols: (); part number: CAP_0603-602433-098,X5R,10UF,16V,20%
C8 C13 C20 C21 C23-C25 C52 C88 C93 = CAP: alternate symbols: (); part number: CAP_0402-A36096-134,X5R,4.7UF,10V,20%
C10-C12 C19 C27 = CAP: alternate symbols: (); part number: CAP_0603-H93459-001,X5R,10UF,6.3V,20%
C14 C15 C28 C29 C32-C35 C38 C39 C45 C46 C48 C49 C55 C56 C67 C68 C72 C74 C75 C77-C80 C82 C85 C90 C92 C96 C97 C99-C103 = CAP: alternate symbols: (); part number: CAP_0402-A36096-030,X7R,0.1UF,16V,10%
C18 C22 C26 C44 C47 C64 C94 C98 = CAP: alternate symbols: (); part number: CAP_0402-A36096-099,X5R,1UF,10V,10%
C30 = CAP: alternate symbols: (); part number: CAP_0603-H93459-001,EMPTY,10UF,6.3V,20%
C31 = CAP: alternate symbols: (); part number: CAP_0402-A36096-111,X5R,1UF,16V,10%
C36 C37 C40 C41 = CAP: alternate symbols: (); part number: CAP_0402-A36095-043,C0G,12PF,50V,5%
C42 = QT_CAP: alternate symbols: (); part number: QT_CAP_0402-J19300-001,CAP,2.2PF,25V,+/-0.1PF
C43 C104 C105 = CAP: alternate symbols: (); part number: CAP_0402-A36096-030,EMPTY,0.1UF,16V,10%
C62 = CAP: alternate symbols: (); part number: CAP_0402-A36096-019,X7R,0.033UF,16V,10%
D1 D2 = LED: alternate symbols: (); part number: LED_A1-H44645-001,LED,GREEN
D3 = LED: alternate symbols: (); part number: LED_A1-H58819-001,LED,YELLOW
D4 = QT_LED: alternate symbols: (); part number: QT_LED_A1-A66229-001,CHIP,GREEN
D6 D7 = QT_DIODE_SCHOTTKY: alternate symbols: (); part number: QT_DIODE_SCHOTTKY_SM-J25836-001,IC,23V,1A
D8 = DIODE_SCHOTTKY: alternate symbols: (); part number: DIODE_SCHOTTKY_SM-H64664-001,DIODE,PMEG2005AEL,0.5A
F1 = FUSE: alternate symbols: (); part number: FUSE_SM-C92281-001,IC,1.5A,6V
FB1 FB3 FB6 FB10 FB12 FB14 FB15 = FERRITE: alternate symbols: (); part number: FERRITE_0603-693286-021,CHIP,30OHM,25%,1A
FB2 FB4 FB5 FB7-FB9 FB11 = FERRITE: alternate symbols: (); part number: FERRITE_0805-656554-026,CHIP,100OHM,25%,4A
FB13 = FERRITE: alternate symbols: (); part number: FERRITE_0603-693286-021,EMPTY,30OHM,25%,1A
FB16 = FERRITE: alternate symbols: (); part number: FERRITE_0603-693286-034,CHIP,120OHM,25%,200MA
FL1 = B9413: alternate symbols: (); part number: B9413_-J11661-001,IC,B9413,
HW1 = LEADERTECH_SMS_201_N_F: alternate symbols: (); part number: LEADERTECH_SMS_201_N_F_-J14056-001,IC,LEADERTECH_SMS_202_N_F,
J1 J2 = HIROSE_USB_MICRO_B_SMT: alternate symbols: (); part number: HIROSE_USB_MICRO_B_SMT_-J11670-001,IC,HIROSE_USB_MICRO_B_SMT,
J3 J5 J6 = TSW-103-07-G-S: alternate symbols: (); part number: TSW-103-07-G-S_-G30105-001,IC,TSW-103-07-G-S,
J4 = QT_CON_1X2: alternate symbols: (); part number: QT_CON_1X2_TH-G95663-001,CON,CON_1X2
J8 = MOLEX_90147_1110: alternate symbols: (); part number: MOLEX_90147_1110_-J11665-001,IC,MOLEX_90147_1110,
J9 J11 = MOLEX_90147_1108: alternate symbols: (); part number: MOLEX_90147_1108_-J11664-001,IC,MOLEX_90147_1108,
J10 = FTSH_105_01_F_DV_K_P_TR: alternate symbols: (); part number: FTSH_105_01_F_DV_K_P_TR_-J11673-001,IC,FTSH_105_01_F_DV_K_P_TR,
J12 = MOLEX_90147_1106: alternate symbols: (); part number: MOLEX_90147_1106_-H77951-001,IC,MOLEX_90147_1106,
J13 = U_FL_R_SMT_1: alternate symbols: (); part number: U_FL_R_SMT_1_-NEED_IPN,EMPTY,U_FL_R_SMT_1,
J14 = HDR_2X25: alternate symbols: (); part number: HDR_2X25_-J11689-001,CON,PRPC025DAAN-RC,
J15 = HDR_2X22: alternate symbols: (); part number: HDR_2X22_-J11692-001,CON,PRPC022DAAN-RC,
J20 J21 = TP_MNT: alternate symbols: (); part number: TP_MNT_-A69956-001,IC,5001,
L1 L2 = CHOKE_4P: alternate symbols: (); part number: CHOKE_4P_0504-752402-026,CHIP,80.0OHM,25%,100MA
L3 = MA_INDUCTOR: alternate symbols: (); part number: MA_INDUCTOR_1P5UH-J18704-001,IND,1.5UH,
L4 L6 = MA_INDUCTOR: alternate symbols: (); part number: MA_INDUCTOR_22UH-J11685-001,IND,22UH,
L5 = MA_INDUCTOR: alternate symbols: (); part number: MA_INDUCTOR_10UH-J13929-001,IND,10UH,
L7 = MA_INDUCTOR: alternate symbols: (); part number: MA_INDUCTOR_2P2NH-J11679-001,IND,2.2NH,
L8 = QT_IND: alternate symbols: (); part number: QT_IND_402-J25163-001,IND,1.5NH,5%,
L9 = QT_IND: alternate symbols: (); part number: QT_IND_402-J25162-001,IND,2.5NH,+/-0.1NH,
L10 = QT_IND: alternate symbols: (); part number: QT_IND_402-J19299-001,IND,4.7NH,+/-0.1NH,250MA
LB1 = LABEL_CHINA_ROHS_10: alternate symbols: (); part number: LABEL_CHINA_ROHS_10_SMT-NA_37331,EMPTY,LABEL_CHINA_ROHS_10
LB3 = LABEL_JEDEC_B4: alternate symbols: (); part number: LABEL_JEDEC_B4_SMT-NA_37329,EMPTY,LABEL_JEDEC_B4
LB4 = LABEL_JEDEC_E1: alternate symbols: (); part number: LABEL_JEDEC_E1_SMT-NA_37330,EMPTY,LABEL_JEDEC_E1
LB5 = LABEL: alternate symbols: (); part number: LABEL_SM-A88430-001,LABEL,SERIAL NUMBER
MH1-MH4 = HW_MH_001: alternate symbols: (); part number: HW_MH_001_-NO_IPN,EMPTY,HW_MH_001,
Q1 Q2 Q4 Q5 = DMN1150UFB-7B: alternate symbols: (); part number: DMN1150UFB-7B_-H70070-001,IC,DMN1150UFB-7B,
R1 R4 R153 R157 R179 R181 R182 R185 R187 R191 = RES: alternate symbols: (); part number: RES_0402-G21796-337,CHIP,2.94K,1%,1/16W
R2 R3 = RES: alternate symbols: (); part number: RES_0402-A93548-013,CHIP,1.1K,1%,1/16W
R5 R9 R15 R25 R30 R52 R57 R64 R66 R104 R107 R113 R114 R124 R125 R127 R128 R131 R138 R143 R156 R160 R166 R168 R169 R183 R184 R192 R195 R196 R198 R204 R214 R215 R239 R243 R262 R263 R266-R269 R281 = RES: alternate symbols: (); part number: RES_0402-A93549-001,CHIP,0,5%,1/16W
R6 R11 R31 R122 R139 R141 R145 R146 R149 R154 R155 R158 R161 R170 R171 R186 R284 = RES: alternate symbols: (SMR0402_OCTO_IA); part number: RES_0402-G85996-033,CHIP,10.0K,0.10%,1/16W
R7 R10 R87 R97 R106 R129 R134 R137 R150 R152 R159 R163 R165 R172-R178 R180 R189 R190 R193 R194 R197 R200-R202 R205 R207 R211 R253 R274-R277 R279 R280 = RES: alternate symbols: (); part number: RES_0402-A93549-027,CHIP,100K,5%,1/16W
R8 R278 = RES: alternate symbols: (); part number: RES_0402-A93548-014,CHIP,1.5K,1%,1/16W
R12 R14 R16 R18-R23 R26 R27 R29 R32 R34-R51 R53-R56 R58-R60 R62 R63 R65 R67-R70 R72-R83 R85 R86 R89 R90 R92-R96 R98 R103 R105 R108 R109 R111 R112 R115-R117 R119 R121 R216-R226 R231 R233-R236 R238 R240-R242 R244 R247 R248 R251 R252 R254-R256 R258-R261 R273 = RES: alternate symbols: (); part number: RES_0402-A93548-503,CHIP,33,1%,1/16W
R13 = RES: alternate symbols: (); part number: RES_0402-A93548-433,CHIP,147K,1%,1/16W
R17 = RES: alternate symbols: (); part number: RES_0603-A93551-036,CHIP,300,5%,1/10W
R24 R28 R148 R151 R167 R270 R271 R285 = RES: alternate symbols: (SMR0402_OCTO_IA); part number: RES_0402-G85996-033,EMPTY,10.0K,0.10%,1/16W
R33 = RES: alternate symbols: (); part number: RES_0402-A93548-672,CHIP,36K,1%,1/16W
R61 R118 R120 R142 R162 R208 R213 R227-R230 R245 R250 R264 R265 R272 = RES: alternate symbols: (); part number: RES_0402-A93549-001,EMPTY,0,5%,1/16W
R71 = RES: alternate symbols: (); part number: RES_0402-H48657-001,CHIP,10M,1%,1/16W
R84 R88 R99-R102 R188 R206 R209 R210 R212 = RES: alternate symbols: (); part number: RES_0402-A93549-027,EMPTY,100K,5%,1/16W
R91 R232 R237 R246 R249 = RES: alternate symbols: (); part number: RES_0402-A93548-209,CHIP,1M,1%,1/16W
R110 = RES: alternate symbols: (SMR0402_OCTO_IA); part number: RES_0402-G21796-088,CHIP,56.2K,1%,1/16W
R123 = RES: alternate symbols: (); part number: RES_0402-A93548-443,CHIP,162K,1%,1/16W
R126 R132 = RES: alternate symbols: (SMR0402_OCTO_IA); part number: RES_0402-G21796-231,CHIP,280K,1%,1/16W
R130 R283 = RES: alternate symbols: (); part number: RES_0402-A93548-620,CHIP,590K,1%,1/16W
R133 = RES: alternate symbols: (); part number: RES_0402-A93548-424,CHIP,226K,1%,1/16W
R135 R136 = RES: alternate symbols: (); part number: RES_0402-A93549-012,CHIP,330,5%,1/16W
R140 = RES: alternate symbols: (SMR0402_OCTO_IA); part number: RES_0402-G21796-389,CHIP,2.05K,1%,1/16W
R144 R199 = QT_RES: alternate symbols: (); part number: QT_RES_0402-A93548-609,CHIP,22.1K,1%,1/16W
R147 = RES: alternate symbols: (); part number: RES_0402-G21796-077,CHIP,475,1%,1/16W
R164 = RES: alternate symbols: (); part number: RES_0402-H48657-001,EMPTY,10M,1%,1/16W
R203 = RES: alternate symbols: (); part number: RES_0402-A36092-128,EMPTY,100K,1%,1/16W
R257 = RES: alternate symbols: (); part number: RES_0402-A93548-450,CHIP,12K,1%,1/16W
R282 = RES: alternate symbols: (); part number: RES_0402-A93548-620,EMPTY,590K,1%,1/16W
RF1 = 2450BM15B0002: alternate symbols: (); part number: 2450BM15B0002_-H98215-001,IC,2450BM15B0002,
RF2 = A10192: alternate symbols: (); part number: A10192_-H85744-001,IC,A10192,
S1 SW1 SW2 = KSR221GLFS: alternate symbols: (); part number: KSR221GLFS_-H98219-001,IC,KSR221GLFS,
SW3 = SW3_SPDT_QT: alternate symbols: (); part number: SW3_SPDT_QT_SM-J16562-001,EMPTY,EG1218A
SW4 = TE_1977104-2: alternate symbols: (); part number: TE_1977104-2_-H98218-001,IC,TE_1977104-2,
TP1 TP3 TP4 = TP: alternate symbols: (); part number: TP_SM-NA_TPC20,EMPTY,TP_C20
U1 U2 = TPS78001: alternate symbols: (); part number: TPS78001_SON-H64475-001,IC,TPS78001
U3 U4 = RCLAMP0502A: alternate symbols: (); part number: RCLAMP0502A_-G48107-001,IC,RCLAMP0502A,
U5 = TLV71333PDBVR: alternate symbols: (); part number: TLV71333PDBVR_-H98350-001,IC,TLV71333PDBVR,
U6 = 93LC46BT_I_OT: alternate symbols: (); part number: 93LC46BT_I_OT_-J19967-001,IC,93LC66BT_I_OT,
U7 = TPS22930A: alternate symbols: (); part number: TPS22930A_-H43461-001,IC,TPS22930A,
U8 U18 = SLG5NT1586V: alternate symbols: (); part number: SLG5NT1586V_-J18705-001,IC,SLG5NT1586V,
U9 U13 U17 = SN74AVCH4T245RSVR: alternate symbols: (); part number: SN74AVCH4T245RSVR_-H47500-001,IC,SN74AVCH4T245RSVR,
U10 = MAX44009EDT: alternate symbols: (); part number: MAX44009EDT_-G92100-001,EMPTY,MAX44009EDT,
U11 = FT2232D: alternate symbols: (); part number: FT2232D_LQFP-E25693-001,IC,FT2232D
U12 = 24AA32A: alternate symbols: (); part number: 24AA32A_DFN-E80542-001,IC,24AA32A
U14 = QT_BMI160: alternate symbols: (); part number: QT_BMI160_-H59665-001,IC,BMI160,
U15 = W25Q80BLUXIG: alternate symbols: (); part number: W25Q80BLUXIG_-H74318-001,EMPTY,W25Q80BLUXIG,
U16 = MIC5504_3P3YMT: alternate symbols: (); part number: MIC5504_3P3YMT_-J11677-001,IC,MIC5504_3P3YMT,
U19 U20 U23 U25 U28 = TC7MBL3257CFT: alternate symbols: (); part number: TC7MBL3257CFT_-H98362-001,IC,TC7MBL3257CFT,
U21 = TMP112: alternate symbols: (); part number: TMP112_-G38922-001,IC,TMP112,
U22 = ATP_BGA_144: alternate symbols: (); part number: ATP_BGA_144_-NEED_IPN,IC,ATP_BGA_144,
U24 U37 = NL17SH14: alternate symbols: (); part number: NL17SH14_-J18707-001   ,IC,NL17SH14,
U26 = R3117K161C: alternate symbols: (); part number: R3117K161C_-H90979-001,IC,R3117K161C,
U27 = TLV702XX: alternate symbols: (); part number: TLV702XX_SOT23-H48581-001,IC,TLV70218
U29 = CC2520RHDT: alternate symbols: (); part number: CC2520RHDT_-H98352-001,IC,CC2520RHDT,
U30 = MDBT40-P128V3: alternate symbols: (); part number: MDBT40-P128V3_-J15562-001,IC,MDBT40-P256V3,
U31 = TPS3831L30DQNR: alternate symbols: (); part number: TPS3831L30DQNR_-H96590-001,IC,TPS3831L30DQNR,
U32 = SN74AUP2G08DQER: alternate symbols: (); part number: SN74AUP2G08DQER_-H12227-001,IC,SN74AUP2G08DQER,
U33 U38 = SN74LVC1G3157DCKR: alternate symbols: (); part number: SN74LVC1G3157DCKR_-G61117-001,IC,SN74LVC1G3157DCKR,
U34 U35 = TP_30MIL: alternate symbols: (); part number: TP_30MIL_-NO_IPN,CON,TP_30MIL,
U36 = SN74LVC1T45DCKR: alternate symbols: (); part number: SN74LVC1T45DCKR_-H90466-001,IC,SN74LVC1T45DCKR,
U39 = QT_TTL1G32: alternate symbols: (); part number: QT_TTL1G32_SM-E60229-001,IC,SN74LVC1G32DCKR
U40 = TPS6303X: alternate symbols: (); part number: TPS6303X_QFN-G49636-001,IC,TPS63030
Y1 = ABMM_6MHZ_B2_T: alternate symbols: (); part number: ABMM_6MHZ_B2_T_-H98363-001,IC,ABMM_6MHZ_B2_T,
Y2 Y4 = CX_FW3200020: alternate symbols: (); part number: CX_FW3200020_-G22404-024,IC,CX_FW3200020,
Y3 = ABS07-32P768KHZ-T: alternate symbols: (); part number: ABS07-32P768KHZ-T_-H32498-001,IC,ABS07-32P768KHZ-T,
Y5 = ABS07-32P768KHZ-T: alternate symbols: (); part number: ABS07-32P768KHZ-T_-E49866-001,IC,ABS07-32P768KHZ-9-T,

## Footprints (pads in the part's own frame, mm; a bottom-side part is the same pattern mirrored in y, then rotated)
HDR_TJV_1X2_50MA
  rect 1.775x1.775 hole 1.4: 1(0,0)
  round 1.775 hole 1.4: 2(0,-5)
LCC6_S20_65DF16X10MA
  rect 0.559x0.356 smd: 1(0,0) 2(0,-0.65) 3(0,-1.3) 4(2.057,-1.3) 5(2.057,-0.65) 6(2.057,0)
  rect 1.016x1.6 smd: 7(1.029,-0.65)
LCC8_16X10_40MA
  custom 0.051x0.051 smd: 1(0,0) 2(0,-0.4) 7(0.813,-0.4) 8(0.813,0)
  custom 0.152x0.152 smd: 3(0,-1.003) 6(0.813,-1.003)
LCC8_20X30_50DF145X165MA
  rect 0.75x0.3 smd: 1(-1.425,0.75) 2(-1.425,0.25) 3(-1.425,-0.25) 4(-1.425,-0.75) 5(1.425,-0.75) 6(1.425,-0.25) 7(1.425,0.25) 8(1.425,0.75)
  rect 1.65x1.45 smd: 9(0,0)
LCC8_30X20_50DF15X13MA
  rect 0.66x0.305 smd: 1(0,0) 2(0,-0.5) 3(0,-1) 4(0,-1.5) 5(2.87,-1.5) 6(2.87,-1) 7(2.87,-0.5) 8(2.87,0)
  rect 1.295x1.295 smd: 9(1.435,-0.75)
LCC10_S25_50DF20X12MA
  rect 0.575x0.3 smd: 1(0,0) 2(0,-0.5) 3(0,-1) 4(0,-1.5) 5(0,-2) 6(2.325,-2) 7(2.325,-1.5) 8(2.325,-1) 9(2.325,-0.5) 10(2.325,0)
  rect 1.2x2 smd: 11(1.163,-1)
QFP48_S70_50MA
  rect 1.778x0.279 smd: 1(-4.191,2.75) 2(-4.191,2.25) 3(-4.191,1.75) 4(-4.191,1.25) 5(-4.191,0.75) 6(-4.191,0.25) 7(-4.191,-0.25) 8(-4.191,-0.75) 9(-4.191,-1.25) 10(-4.191,-1.75) 11(-4.191,-2.25) 12(-4.191,-2.75) 25(4.191,-2.75) 26(4.191,-2.25) 27(4.191,-1.75) 28(4.191,-1.25) 29(4.191,-0.75) 30(4.191,-0.25) 31(4.191,0.25) 32(4.191,0.75) 33(4.191,1.25) 34(4.191,1.75) 35(4.191,2.25) 36(4.191,2.75)
  rect 0.279x1.778 smd: 13(-2.75,-4.191) 14(-2.25,-4.191) 15(-1.75,-4.191) 16(-1.25,-4.191) 17(-0.75,-4.191) 18(-0.25,-4.191) 19(0.25,-4.191) 20(0.75,-4.191) 21(1.25,-4.191) 22(1.75,-4.191) 23(2.25,-4.191) 24(2.75,-4.191) 37(2.75,4.191) 38(2.25,4.191) 39(1.75,4.191) 40(1.25,4.191) 41(0.75,4.191) 42(0.25,4.191) 43(-0.25,4.191) 44(-0.75,4.191) 45(-1.25,4.191) 46(-1.75,4.191) 47(-2.25,4.191) 48(-2.75,4.191)
QT_CN_HIROSE_ZX62D_B_5P8
  rect 0.381x1.346 smd: 1(0,0) 2(0.65,0) 3(1.3,0) 4(1.951,0) 5(2.601,0)
  oval 1.041x1.245 hole 0.66x0.838: 6(3.725,0.1) 7(-1.125,0.1)
  custom 0.475x0.475 hole 1.524x0.813: 8(-2.3,-2.677) 11(4.9,-2.677)
  rect 1.801x1.9 smd: 9(0.15,-2.677) 10(2.45,-2.677)
QT_IND_MDKK3030_0P8X2P7
  rect 0.8x2.7 smd: 1(-1.1,0) 2(1.1,0)
QT_IND_PSB12101T_1P45X1P2
  rect 0.5x1.2 smd: 1(-0.45,0) 2(0.45,0)
QT_JSMM_MOLEX_90147_1106_PTH031
  rect 1.168x1.168 hole 0.787: 1(0,0)
  round 1.168 hole 0.787: 2(0,-2.54) 3(0,-5.08) 4(0,-7.62) 5(0,-10.16) 6(0,-12.7)
QT_JSMM_MOLEX_90147_1108_PTH031
  rect 1.168x1.168 hole 0.787: 1(0,0)
  round 1.168 hole 0.787: 2(0,-2.54) 3(0,-5.08) 4(0,-7.62) 5(0,-10.16) 6(0,-12.7) 7(0,-15.24) 8(0,-17.78)
QT_JSMM_MOLEX_90147_1110_PTH031
  rect 1.168x1.168 hole 0.787: 1(0,0)
  round 1.168 hole 0.787: 2(0,-2.54) 3(0,-5.08) 4(0,-7.62) 5(0,-10.16) 6(0,-12.7) 7(0,-15.24) 8(0,-17.78) 9(0,-20.32) 10(0,-22.86)
QT_JSMM_SAMTEC_FTSH_105
  rect 2.794x0.737 smd: 1(2.032,-2.54) 2(-2.032,-2.54) 3(2.032,-1.27) 4(-2.032,-1.27) 5(2.032,0) 6(-2.032,0) 7(2.032,1.27) 8(-2.032,1.27) 9(2.032,2.54) 10(-2.032,2.54)
QT_JTHI_HDR_2X22_0P040D
  rect 1.524x1.524 hole 1.016: 1(0,0)
  round 1.524 hole 1.016: 2(2.54,0) 3(0,-2.54) 4(2.54,-2.54) 5(0,-5.08) 6(2.54,-5.08) 7(0,-7.62) 8(2.54,-7.62) 9(0,-10.16) 10(2.54,-10.16) 11(0,-12.7) 12(2.54,-12.7) 13(0,-15.24) 14(2.54,-15.24) 15(0,-17.78) 16(2.54,-17.78) 17(0,-20.32) 18(2.54,-20.32) 19(0,-22.86) 20(2.54,-22.86) 21(0,-25.4) 22(2.54,-25.4) 23(0,-27.94) 24(2.54,-27.94) 25(0,-30.48) 26(2.54,-30.48) 27(0,-33.02) 28(2.54,-33.02) 29(0,-35.56) 30(2.54,-35.56) 31(0,-38.1) 32(2.54,-38.1) 33(0,-40.64) 34(2.54,-40.64) 35(0,-43.18) 36(2.54,-43.18) 37(0,-45.72) 38(2.54,-45.72) 39(0,-48.26) 40(2.54,-48.26) 41(0,-50.8) 42(2.54,-50.8) 43(0,-53.34) 44(2.54,-53.34)
QT_JTHI_HDR_2X25_0P040D
  rect 1.524x1.524 hole 1.016: 1(0,0)
  round 1.524 hole 1.016: 2(2.54,0) 3(0,-2.54) 4(2.54,-2.54) 5(0,-5.08) 6(2.54,-5.08) 7(0,-7.62) 8(2.54,-7.62) 9(0,-10.16) 10(2.54,-10.16) 11(0,-12.7) 12(2.54,-12.7) 13(0,-15.24) 14(2.54,-15.24) 15(0,-17.78) 16(2.54,-17.78) 17(0,-20.32) 18(2.54,-20.32) 19(0,-22.86) 20(2.54,-22.86) 21(0,-25.4) 22(2.54,-25.4) 23(0,-27.94) 24(2.54,-27.94) 25(0,-30.48) 26(2.54,-30.48) 27(0,-33.02) 28(2.54,-33.02) 29(0,-35.56) 30(2.54,-35.56) 31(0,-38.1) 32(2.54,-38.1) 33(0,-40.64) 34(2.54,-40.64) 35(0,-43.18) 36(2.54,-43.18) 37(0,-45.72) 38(2.54,-45.72) 39(0,-48.26) 40(2.54,-48.26) 41(0,-50.8) 42(2.54,-50.8) 43(0,-53.34) 44(2.54,-53.34) 45(0,-55.88) 46(2.54,-55.88) 47(0,-58.42) 48(2.54,-58.42) 49(0,-60.96) 50(2.54,-60.96)
QT_JTHI_SAMTEC_TSW_103_07_G_S
  rect 1.524x1.524 hole 1.016: 1(0,0)
  round 1.524 hole 1.016: 2(0,-2.54) 3(0,-5.08)
QT_LCC14_30X25_50MA
  rect 0.675x0.25 smd: 1(0,0) 2(0,-0.5) 3(0,-1) 4(0,-1.5) 8(2.525,-1.5) 9(2.525,-1) 10(2.525,-0.5) 11(2.525,0)
  rect 0.25x0.675 smd: 5(0.763,-1.763) 6(1.262,-1.763) 7(1.763,-1.763) 12(1.763,0.262) 13(1.262,0.262) 14(0.763,0.262)
QT_LCC42_180X100_70MA
  rect 1.699x0.5 smd: 1(-4.75,4) 2(-4.75,3.3) 3(-4.75,-0.9) 4(-4.75,-1.6) 5(-4.75,-2.3) 6(-4.75,-3) 7(-4.75,-3.7) 8(-4.75,-4.4) 9(-4.75,-5.1) 10(-4.75,-5.8) 11(-4.75,-6.5) 12(-4.75,-7.2) 26(4.75,-7.2) 27(4.75,-6.5) 28(4.75,-5.8) 29(4.75,-5.1) 30(4.75,-4.4) 31(4.75,-3.7) 32(4.75,-3) 33(4.75,-2.3) 34(4.75,-1.6) 35(4.75,-0.9) 36(4.75,-0.2) 37(4.75,0.5) 38(4.75,1.2) 39(4.75,1.9) 40(4.75,2.6) 41(4.75,3.3) 42(4.75,4)
  rect 0.5x1.699 smd: 13(-4.2,-8.75) 14(-3.5,-8.75) 15(-2.8,-8.75) 16(-2.1,-8.75) 17(-1.4,-8.75) 18(-0.7,-8.75) 19(0,-8.75) 20(0.7,-8.75) 21(1.4,-8.75) 22(2.1,-8.75) 23(2.8,-8.75) 24(3.5,-8.75) 25(4.2,-8.75)
QT_LSMI_COILCRAFT_0402HP
  rect 0.356x0.66 smd: 1(0,0) 2(0.864,0)
QT_MHTHI_PTH_250R118
  round 6.35 hole 2.997: 1(0,0)
QT_P2XSON-8
  rect 0.533x0.203 smd: 1(-0.337,0.525) 2(-0.337,0.175) 3(-0.337,-0.175) 4(-0.337,-0.525) 5(0.337,-0.525) 6(0.337,-0.175) 7(0.337,0.175) 8(0.337,0.525)
QT_QSMM_SOT883B
  rect 0.399x0.249 smd: 1(-0.35,0.225) 2(-0.35,-0.225)
  rect 0.399x0.701 smd: 3(0.35,0)
QT_RFSMM_ANTENOVA_A10192
  rect 0.813x0.991 smd: 1(-1.4,0.8) 2(1.4,0) 3(-1.4,-0.8)
QT_RFSMM_JOHANSON_2450BM15B0002
  rect 0.356x1.016 smd: 1(0.65,0.9) 2(0,0.9) 3(-0.65,0.9) 4(-0.65,-0.9) 5(0,-0.9) 6(0.65,-0.9)
QT_SMCC_LEADERTECH_SMS_201
  custom 1.143x1.143 smd: 1(-8.166,8.166) 3(-8.166,-8.166) 5(8.166,-8.166) 7(8.166,8.166)
  rect 0.991x3.81 smd: 2(-8.166,0) 6(8.166,0)
  rect 3.81x0.991 smd: 4(0,-8.166) 8(0,8.166)
QT_SOD_323
  rect 1.06x0.54 smd: 1(0,0) 2(2.14,0)
QT_SOT_953
  rect 0.35x0.2 smd: 1(0,0) 2(0,-0.35) 3(0,-0.7) 4(0.85,-0.7) 5(0.85,0)
QT_SSMI_CK_KSR221GLFS
  rect 1.499x1.397 smd: 1(0,0) 2(6.5,0)
QT_SWTHI_TYCO_1977104_2
  rect 1.27x1.27 hole 0.813: 1(0,0)
  round 1.27 hole 0.813: 2(0,-2.54) 3(0,-5.08) 4(0,-7.62) 5(0,-10.16)
QT_TDFN_4
  custom 0.062x0.062 smd: 1(0,0) 2(-0.035,-0.65) 3(0.865,-0.65) 4(0.865,0)
  custom 0.17x0.17 smd: 5(0.415,-0.325)
QT_TPSMI_30
  round 0.762 smd: 1(0,0)
QT_USMI_SOT235
  rect 0.599x1.049 smd: 1(-0.95,-1.35) 2(0,-1.35) 3(0.95,-1.35) 4(0.95,1.35) 5(-0.95,1.35)
QT_USMI_SOT666
  rect 0.305x0.838 smd: 1(-0.5,-0.724) 2(0,-0.724) 3(0.5,-0.724) 4(0.5,0.724) 5(0,0.724) 6(-0.5,0.724)
QT_USMM_4YZV
  round 0.254 smd: A1(-0.25,0.25) A2(0.25,0.25) B1(-0.25,-0.25) B2(0.25,-0.25)
QT_USMM_6_UTDFN_OPTO
  rect 0.48x0.361 smd: 1(-0.925,0.65) 2(-0.925,0) 3(-0.925,-0.65) 4(0.925,-0.65) 5(0.925,0) 6(0.925,0.65)
  rect 0.711x1.4 smd: 7(0,0)
QT_USMM_PG_LFBGA144_10
  round 0.35 smd: A1(-4.418,4.418) A2(-3.618,4.418) A3(-2.818,4.418) A4(-2.018,4.418) A5(-1.218,4.418) A6(-0.418,4.418) A7(0.382,4.418) A8(1.182,4.418) A9(1.982,4.418) A10(2.782,4.418) A11(3.582,4.418) A12(4.382,4.418) B1(-4.418,3.618) B2(-3.618,3.618) B3(-2.818,3.618) B4(-2.018,3.618) B5(-1.218,3.618) B6(-0.418,3.618) B7(0.382,3.618) B8(1.182,3.618) B9(1.982,3.618) B10(2.782,3.618) B11(3.582,3.618) B12(4.382,3.618) C1(-4.418,2.818) C2(-3.618,2.818) C3(-2.818,2.818) C4(-2.018,2.818) C5(-1.218,2.818) C6(-0.418,2.818) C7(0.382,2.818) C8(1.182,2.818) C9(1.982,2.818) C10(2.782,2.818) C11(3.582,2.818) C12(4.382,2.818) D1(-4.418,2.018) D2(-3.618,2.018) D3(-2.818,2.018) D4(-2.018,2.018) D5(-1.218,2.018) D6(-0.418,2.018) D7(0.382,2.018) D8(1.182,2.018) D9(1.982,2.018) D10(2.782,2.018) D11(3.582,2.018) D12(4.382,2.018) E1(-4.418,1.218) E2(-3.618,1.218) E3(-2.818,1.218) E4(-2.018,1.218) E5(-1.218,1.218) E6(-0.418,1.218) E7(0.382,1.218) E8(1.182,1.218) E9(1.982,1.218) E10(2.782,1.218) E11(3.582,1.218) E12(4.382,1.218) F1(-4.418,0.418) F2(-3.618,0.418) F3(-2.818,0.418) F4(-2.018,0.418) F5(-1.218,0.418) F6(-0.418,0.418) F7(0.382,0.418) F8(1.182,0.418) F9(1.982,0.418) F10(2.782,0.418) F11(3.582,0.418) F12(4.382,0.418) G1(-4.418,-0.382) G2(-3.618,-0.382) G3(-2.818,-0.382) G4(-2.018,-0.382) G5(-1.218,-0.382) G6(-0.418,-0.382) G7(0.382,-0.382) G8(1.182,-0.382) G9(1.982,-0.382) G10(2.782,-0.382) G11(3.582,-0.382) G12(4.382,-0.382) H1(-4.418,-1.182) H2(-3.618,-1.182) H3(-2.818,-1.182) H4(-2.018,-1.182) H5(-1.218,-1.182) H6(-0.418,-1.182) H7(0.382,-1.182) H8(1.182,-1.182) H9(1.982,-1.182) H10(2.782,-1.182) H11(3.582,-1.182) H12(4.382,-1.182) J1(-4.418,-1.982) J2(-3.618,-1.982) J3(-2.818,-1.982) J4(-2.018,-1.982) J5(-1.218,-1.982) J6(-0.418,-1.982) J7(0.382,-1.982) J8(1.182,-1.982) J9(1.982,-1.982) J10(2.782,-1.982) J11(3.582,-1.982) J12(4.382,-1.982) K1(-4.418,-2.782) K2(-3.618,-2.782) K3(-2.818,-2.782) K4(-2.018,-2.782) K5(-1.218,-2.782) K6(-0.418,-2.782) K7(0.382,-2.782) K8(1.182,-2.782) K9(1.982,-2.782) K10(2.782,-2.782) K11(3.582,-2.782) K12(4.382,-2.782) L1(-4.418,-3.582) L2(-3.618,-3.582) L3(-2.818,-3.582) L4(-2.018,-3.582) L5(-1.218,-3.582) L6(-0.418,-3.582) L7(0.382,-3.582) L8(1.182,-3.582) L9(1.982,-3.582) L10(2.782,-3.582) L11(3.582,-3.582) L12(4.382,-3.582) M1(-4.418,-4.382) M2(-3.618,-4.382) M3(-2.818,-4.382) M4(-2.018,-4.382) M5(-1.218,-4.382) M6(-0.418,-4.382) M7(0.382,-4.382) M8(1.182,-4.382) M9(1.982,-4.382) M10(2.782,-4.382) M11(3.582,-4.382) M12(4.382,-4.382)
QT_USMM_QCS5F_B9413
  rect 0.249x0.325 smd: 1(-0.5,0) 2(0,-0.288) 3(0.5,-0.288) 4(0.5,0.288) 5(0,0.288)
QT_USMM_SC70_5
  rect 0.899x0.399 smd: 1(0,0) 2(0,-0.65) 3(0,-1.3) 4(2.2,-1.3) 5(2.2,0)
QT_USMM_SC70_6
  rect 0.899x0.399 smd: 1(0,0) 2(0,-0.65) 3(0,-1.3) 4(2.2,-1.3) 5(2.2,-0.65) 6(2.2,0)
QT_USMM_UFQFN16
  rect 0.762x0.203 smd: 1(-0.72,0.6)
  rect 0.66x0.203 smd: 2(-0.77,0.2) 3(-0.77,-0.2) 4(-0.77,-0.6) 9(0.77,-0.6) 10(0.77,-0.2) 11(0.77,0.2) 12(0.77,0.6)
  rect 0.203x0.66 smd: 5(-0.6,-1.17) 6(-0.2,-1.17) 7(0.2,-1.17) 8(0.6,-1.17) 13(0.6,1.17) 14(0.2,1.17) 15(-0.2,1.17) 16(-0.6,1.17)
QT_USMM_VQFN28
  custom 0.07x0.07 smd: 1(-2.413,1.501) 2(-2.413,1.001) 3(-2.413,0.5) 4(-2.413,0) 5(-2.413,-0.5) 6(-2.413,-1.001) 7(-2.413,-1.501) 8(-1.501,-2.413) 9(-1.001,-2.413) 10(-0.5,-2.413) 11(0,-2.413) 12(0.5,-2.413) 13(1.001,-2.413) 14(1.501,-2.413) 15(2.413,-1.501) 16(2.413,-1.001) 17(2.413,-0.5) 18(2.413,0) 19(2.413,0.5) 20(2.413,1.001) 21(2.413,1.501) 22(1.501,2.413) 23(1.001,2.413) 24(0.5,2.413) 25(0,2.413) 26(-0.5,2.413) 27(-1.001,2.413) 28(-1.501,2.413)
  rect 3.15x3.15 smd: 29(0,0)
QT_YSMM_ABRACON_ABMM
  rect 2.159x1.397 smd: 1(-3.15,-1.27) 2(3.15,-1.27) 3(3.15,1.27) 4(-3.15,1.27)
QT_YSMM_PSE_FW3200020
  rect 0.889x0.787 smd: 1(-0.699,-0.546) 2(0.699,-0.546) 3(0.699,0.546) 4(-0.699,0.546)
SCR1006MA
  rect 0.35x0.65 smd: 1(0,0) 2(0.7,0)
SFB0603IA
  rect 0.889x0.762 smd: 1(0,0) 2(1.27,0)
SFB0603IB
  rect 0.94x0.94 smd: 1(0,0) 2(1.448,0)
SFB0805IA
  rect 1.016x1.27 smd: 1(0,0) 2(1.778,0)
SFU1206IA
  rect 1.448x1.803 smd: 1(0,0) 2(2.946,0)
SLED0603IB
  rect 0.787x0.787 smd: 1(0,0) 2(1.626,0)
SLEDR16X08MA
  rect 0.787x0.787 smd: 1(0,0) 2(1.626,0)
SLEDR0603IA
  rect 0.787x0.787 smd: 1(0,0) 2(1.626,0)
SMC0402IA
  rect 0.508x0.508 smd: 1(0,0) 2(0.889,0)
SMC0402IB
  rect 0.737x0.559 smd: 1(0,0) 2(0.94,0)
SMC0603IA
  rect 0.889x0.762 smd: 1(0,0) 2(1.397,0)
SMC0603IB
  rect 0.889x0.94 smd: 1(0,0) 2(1.397,0)
SMI4_10X13MA
  rect 1.016x0.356 smd: 1(0,0) 2(1.524,0) 3(1.524,-0.55) 4(0,-0.55)
SMI0402IA
  rect 0.508x0.61 smd: 1(0,0) 2(0.889,0)
SMP_SJV_1_2EM_MA
  rect 0.991x1.041 smd: 1(0,0)
  rect 1.041x2.21 smd: 2(-1.475,-1.521) 3(1.475,-1.521)
SMR0402IA
  rect 0.508x0.508 smd: 1(0,0) 2(0.889,0)
SMR0603IA
  rect 0.889x0.762 smd: 1(0,0) 2(1.397,0)
SMY32X15MA
  rect 0.991x1.803 smd: 1(0,0) 2(2.489,0)
SOT23_5MC
  rect 1.067x0.61 smd: 1(0,0) 2(0,-0.95) 3(0,-1.9) 4(2.667,-1.9) 5(2.667,0)
SOT23_6MC
  rect 1.1x0.6 smd: 1(-0.26,0) 2(-0.26,-0.95) 3(-0.26,-1.9) 4(2.54,-1.9) 5(2.54,-0.95) 6(2.54,0)
SOT563A
  rect 0.61x0.305 smd: 1(0,0) 2(0,-0.5) 3(0,-1) 4(1.448,-1) 5(1.448,-0.5) 6(1.448,0)
SW3VS_116X40_250MA
  rect 1.475x1.475 hole 1.1: 1(0,0)
  round 1.475 hole 1.1: 2(0,-2.5) 3(0,-5)
TP_C20
  round 0.508 smd: 1(0,0)
TP_C55P40A65
  round 1.397 hole 1.016: 1(0,0)
TSSOP16_50X44_65MA
  rect 1.778x0.305 smd: 1(0,0) 2(0,-0.65) 3(0,-1.3) 4(0,-1.95) 5(0,-2.6) 6(0,-3.25) 7(0,-3.9) 8(0,-4.55) 9(5.842,-4.55) 10(5.842,-3.9) 11(5.842,-3.25) 12(5.842,-2.6) 13(5.842,-1.95) 14(5.842,-1.3) 15(5.842,-0.65) 16(5.842,0)
unnamed#2
  round 0 hole 1.6 unplated: (-3,0) (3,0)

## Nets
AVDD_A_RADIO: C35.1(A) R104.2(B) R107.2(B) U29.11(AVDD5)
AVDD_B_RADIO: C38.1(A) R113.2(B) U29.14(AVDD3) U29.16(AVDD2)
AVDD_C_RADIO: C39.1(A) R114.2(B) U29.20(AVDD1) U29.22(AVDD4) U29.24(AVDD_GUARD)
DVDD_RADIO: C33.1(A) R104.1(A) U29.8(DVDD)
